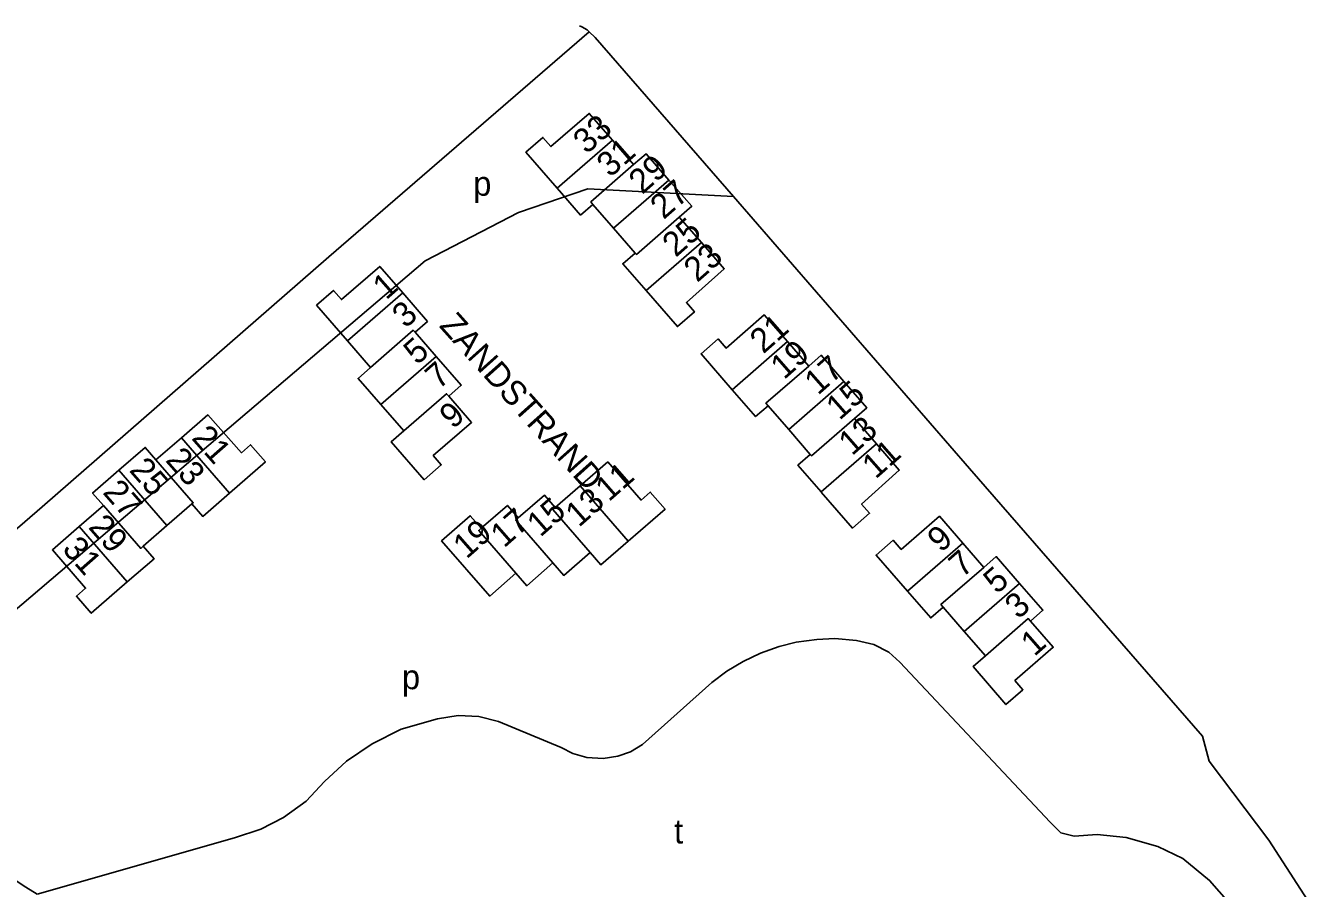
# Model space of a CAD drawing. Extents: x 155696 to 157795, y 382328 to 384028.
# Drawn here: x 156412.1 to 156623.9, y 383886.8 to 384028.1 of the extents above; entities that cross this region are included whole.
import ezdxf

# ---------------------------------------------------------------- set-up
doc = ezdxf.new("R2010")
doc.units = 0
for name, color, linetype in [('BLT_Basislijn', 7, 'Continuous'), ('BLT_Centroide', 7, 'Continuous'), ('BLT_Huisnummer_zonder_bebouwing', 7, 'Continuous'), ('BLT_Plantopo', 7, 'Continuous'), ('BLT_Straatnaam_verkleind', 7, 'Continuous')]:
    doc.layers.add(name, color=color, linetype=linetype)

msp = doc.modelspace()

# ---------------------------------------------------------------- linework, layer by layer
at = {"layer": 'BLT_Basislijn'}
for p, q in [((156461.79, 383990.25), (156504.46, 384027.08)), ((156505.42, 384026.19), (156528.08, 384000.1)), ((156528.08, 384000.1), (156566.77, 383955.57)), ((156414.79, 383949.31), (156461.79, 383990.25)), ((156409.95, 383945.11), (156414.79, 383949.31)), ((156412.14, 383886.98), (156413.99, 383885.83))]:
    msp.add_line(p, q, dxfattribs=at)
for points in [[(156502.88, 384028.08), (156503.25, 384027.89), (156504.09, 384027.43), (156504.46, 384027.08)], [(156504.46, 384027.08), (156505.42, 384026.19)], [(156528.08, 384000.1), (156504.25, 384001.4), (156492.87, 383997.5), (156477.56, 383989.59), (156410.02, 383932.03), (156404.54, 383932.08)], [(156566.77, 383955.57), (156604.92, 383911.72), (156606.02, 383907.63)], [(156368.17, 383937.56), (156368.9, 383931.22), (156371.06, 383924.08), (156377.9, 383913.69), (156388.58, 383902.37), (156412.14, 383886.98)], [(156413.99, 383885.83), (156446.3, 383895.07), (156450.62, 383896.48), (156454.35, 383898.42), (156458.05, 383901.08), (156461.06, 383904.3), (156464.67, 383907.66), (156468.87, 383910.5), (156473.63, 383912.86), (156479.58, 383914.57), (156482.98, 383915.1), (156486.36, 383914.96), (156489.59, 383914.12), (156499.84, 383909.87), (156501.77, 383908.89), (156504.06, 383908.23), (156506.72, 383908.06), (156509.12, 383908.45), (156511.2, 383909.16), (156513.17, 383910.36), (156524.55, 383920.52), (156526.98, 383922.36), (156529.69, 383923.98), (156532.5, 383925.34), (156535.56, 383926.39), (156538.37, 383927.11), (156541.74, 383927.54), (156544.69, 383927.7), (156548.23, 383927.41), (156551.09, 383926.73), (156553.54, 383925.49), (156555.37, 383923.86), (156579.98, 383897.63), (156581.74, 383895.89), (156583.92, 383895.33), (156587.67, 383895.61), (156592.45, 383895.15), (156597.64, 383893.68), (156601.7, 383891.69), (156606.1, 383888.09), (156609.26, 383884.46)], [(156606.02, 383907.63), (156615.79, 383894.68), (156623.9, 383882.19)]]:
    msp.add_lwpolyline(points, dxfattribs=at)
at = {"layer": 'BLT_Plantopo'}
for p, q in [((156508.27, 384009.34), (156499.21, 384001.47)), ((156511.73, 384005.35), (156508.27, 384009.34)), ((156517.51, 384002.82), (156508.45, 383994.95)), ((156505.06, 383998.84), (156508.45, 383994.95)), ((156522.83, 383992.58), (156519.21, 383996.75)), ((156508.45, 383994.95), (156511.99, 383990.87)), ((156522.83, 383992.58), (156513.76, 383984.72)), ((156473.89, 383984.33), (156464.84, 383976.46)), ((156459.75, 383982.31), (156464.84, 383976.46)), ((156479.37, 383973.91), (156475.91, 383977.89)), ((156464.84, 383976.46), (156468.61, 383972.11)), ((156536.96, 383976.35), (156527.9, 383968.48)), ((156540.42, 383972.36), (156536.96, 383976.35)), ((156479.37, 383973.91), (156470.32, 383966.04)), ((156546.2, 383969.83), (156537.14, 383961.96)), ((156470.32, 383966.04), (156474.05, 383961.73)), ((156533.75, 383965.85), (156537.14, 383961.96)), ((156551.52, 383959.59), (156547.9, 383963.76)), ((156437.63, 383960.61), (156433.46, 383956.99)), ((156437.63, 383960.61), (156445.49, 383951.54)), ((156537.14, 383961.96), (156540.68, 383957.88)), ((156551.52, 383959.59), (156542.45, 383951.73)), ((156507.5, 383956.66), (156502.99, 383952.74)), ((156427.39, 383955.29), (156435.26, 383946.23)), ((156502.99, 383952.74), (156498.89, 383949.18)), ((156510.86, 383943.69), (156502.99, 383952.74)), ((156424.86, 383949.51), (156420.87, 383946.05)), ((156435.26, 383946.23), (156439.33, 383949.77)), ((156420.87, 383946.05), (156428.74, 383936.99)), ((156431.36, 383942.84), (156435.26, 383946.23)), ((156565.65, 383943.36), (156556.59, 383935.49)), ((156569.11, 383939.37), (156565.65, 383943.36)), ((156574.97, 383936.75), (156565.91, 383928.88)), ((156562.45, 383932.87), (156565.91, 383928.88)), ((156565.91, 383928.88), (156569.37, 383924.9))]:
    msp.add_line(p, q, dxfattribs=at)
for points in [[(156508.27, 384009.34), (156504.45, 384013.73), (156498.18, 384008.29), (156496.87, 384009.8), (156494.08, 384007.37), (156499.21, 384001.47)], [(156517.51, 384002.82), (156513.77, 384007.12), (156511.73, 384005.35)], [(156505.06, 383998.84), (156504.71, 383999.25), (156511.73, 384005.35)], [(156519.21, 383996.75), (156521.25, 383998.52), (156517.51, 384002.82)], [(156499.21, 384001.47), (156503.03, 383997.07), (156505.06, 383998.84)], [(156511.99, 383990.87), (156512.19, 383990.65), (156519.21, 383996.75)], [(156513.77, 383984.71), (156518.9, 383978.81), (156521.7, 383981.23), (156520.38, 383982.74), (156526.57, 383988.28), (156522.83, 383992.58)], [(156511.99, 383990.87), (156509.95, 383989.1), (156513.76, 383984.72)], [(156473.89, 383984.33), (156470.12, 383988.67), (156463.85, 383983.23), (156462.54, 383984.74), (156459.75, 383982.31)], [(156475.91, 383977.89), (156477.95, 383979.66), (156473.89, 383984.33)], [(156536.96, 383976.35), (156533.14, 383980.74), (156526.87, 383975.3), (156525.56, 383976.81), (156522.77, 383974.38), (156527.9, 383968.48)], [(156468.61, 383972.11), (156475.63, 383978.21), (156475.91, 383977.89)], [(156481.43, 383967.43), (156483.47, 383969.2), (156479.37, 383973.91)], [(156546.2, 383969.83), (156542.46, 383974.13), (156540.42, 383972.36)], [(156468.61, 383972.11), (156466.58, 383970.34), (156470.32, 383966.04)], [(156533.75, 383965.85), (156533.4, 383966.26), (156540.42, 383972.36)], [(156527.9, 383968.48), (156531.72, 383964.08), (156533.75, 383965.85)], [(156547.9, 383963.76), (156549.94, 383965.53), (156546.2, 383969.83)], [(156474.05, 383961.73), (156472.02, 383959.96), (156477.42, 383953.74), (156480.21, 383956.17), (156478.9, 383957.68), (156485.17, 383963.13), (156481.43, 383967.43)], [(156474.05, 383961.73), (156481.07, 383967.83), (156481.43, 383967.43)], [(156445.5, 383951.55), (156451.4, 383956.68), (156448.97, 383959.47), (156447.46, 383958.16), (156441.93, 383964.35), (156437.63, 383960.61)], [(156540.68, 383957.88), (156540.88, 383957.66), (156547.9, 383963.76)], [(156433.46, 383956.99), (156431.69, 383959.02), (156427.39, 383955.29)], [(156540.68, 383957.88), (156538.64, 383956.11), (156542.45, 383951.73)], [(156542.46, 383951.72), (156547.59, 383945.82), (156550.39, 383948.24), (156549.07, 383949.75), (156555.26, 383955.29), (156551.52, 383959.59)], [(156439.33, 383949.77), (156439.56, 383949.97), (156433.46, 383956.99)], [(156510.86, 383943.69), (156516.88, 383948.91), (156514.45, 383951.71), (156512.94, 383950.4), (156507.5, 383956.66)], [(156427.39, 383955.29), (156423.08, 383951.55), (156424.86, 383949.51)], [(156439.33, 383949.77), (156441.11, 383947.73), (156445.49, 383951.54)], [(156431.36, 383942.84), (156430.96, 383942.49), (156424.86, 383949.51)], [(156492.82, 383947.48), (156491.05, 383949.52), (156486.74, 383945.78)], [(156498.89, 383949.18), (156497.12, 383951.22), (156492.82, 383947.48)], [(156486.74, 383945.78), (156484.97, 383947.82), (156480.26, 383943.72), (156488.14, 383934.67), (156492.44, 383938.41)], [(156498.51, 383940.11), (156492.41, 383947.13), (156492.82, 383947.48)], [(156498.89, 383949.18), (156498.48, 383948.83), (156504.58, 383941.81)], [(156565.65, 383943.36), (156561.83, 383947.75), (156555.57, 383942.31), (156554.25, 383943.82), (156551.46, 383941.39), (156556.59, 383935.49)], [(156420.87, 383946.05), (156416.48, 383942.23), (156421.92, 383935.96), (156420.41, 383934.65), (156422.84, 383931.86), (156428.74, 383936.99)], [(156486.74, 383945.78), (156486.34, 383945.43), (156492.44, 383938.41)], [(156504.58, 383941.81), (156506.36, 383939.77), (156510.86, 383943.69)], [(156428.74, 383936.99), (156433.14, 383940.8), (156431.36, 383942.84)], [(156498.51, 383940.11), (156500.28, 383938.07), (156504.58, 383941.81)], [(156574.97, 383936.75), (156571.15, 383941.15), (156569.11, 383939.37)], [(156492.44, 383938.41), (156494.21, 383936.37), (156498.51, 383940.11)], [(156562.45, 383932.87), (156562.09, 383933.27), (156569.11, 383939.37)], [(156576.75, 383930.59), (156578.79, 383932.36), (156574.97, 383936.75)], [(156556.59, 383935.49), (156560.41, 383931.09), (156562.45, 383932.87)], [(156569.37, 383924.9), (156567.34, 383923.12), (156572.74, 383916.91), (156575.53, 383919.33), (156574.22, 383920.84), (156580.49, 383926.29), (156576.75, 383930.59)], [(156569.37, 383924.9), (156576.39, 383931), (156576.75, 383930.59)]]:
    msp.add_lwpolyline(points, dxfattribs=at)

# ---------------------------------------------------------------- texts
at = {"layer": 'BLT_Centroide'}
for s, p in [('p', (156485.44, 384000.25)), ('p', (156473.76, 383919.42)), ('t', (156518.36, 383894.15))]:
    msp.add_text(s, height=4, dxfattribs=at).set_placement(p)
at = {"layer": 'BLT_Huisnummer_zonder_bebouwing'}
for s, rotation, p in [('33', 41.2925, (156504.02, 384006.94)), ('31', 41.2925, (156507.88, 384003.12)), ('29', 41.2925, (156513.13, 384000.37)), ('27', 41.2925, (156516.65, 383996.25)), ('25', 41.2925, (156518.63, 383990.05)), ('23', 41.2925, (156522.15, 383985.94)), ('1', 41.2925, (156471.18, 383983.08)), ('3', 41.2925, (156474.36, 383978.41)), ('21', 41.2925, (156532.98, 383974.25)), ('5', 41.2925, (156476.24, 383972.41)), ('19', 41.2925, (156536.37, 383970.02)), ('7', 41.2925, (156479.79, 383968.41)), ('17', 41.2925, (156541.93, 383967.47)), ('15', 41.2925, (156545.46, 383963.36)), ('9', 41.2925, (156482.12, 383961.91)), ('21', 311.2925, (156439.16, 383960.48)), ('13', 41.2925, (156547.51, 383957.55)), ('23', 311.2925, (156434.88, 383956.86)), ('11', 41.2925, (156551.37, 383953.73)), ('25', 311.2925, (156428.94, 383955.22)), ('11', 41.2925, (156507.66, 383950.02)), ('27', 311.2925, (156424.59, 383951.59)), ('13', 41.2925, (156502.76, 383945.83)), ('15', 41.2925, (156496.44, 383944.22)), ('29', 311.2925, (156422.24, 383945.89)), ('17', 41.2925, (156490.49, 383942.45)), ('19', 41.2925, (156484.35, 383940.64)), ('9', 41.2925, (156562.07, 383941.68)), ('31', 311.2925, (156417.95, 383942.27)), ('7', 41.2925, (156565.58, 383937.56)), ('5', 41.2925, (156571.25, 383934.88)), ('3', 41.2925, (156574.77, 383930.76)), ('1', 41.2925, (156577.39, 383924.67))]:
    msp.add_text(s, height=4, rotation=rotation, dxfattribs=at).set_placement(p)
at = {"layer": 'BLT_Straatnaam_verkleind'}
msp.add_text('ZANDSTRAND', height=4, rotation=311.8215, dxfattribs=at).set_placement((156479.74, 383978.87))

doc.saveas('drawing.dxf')
